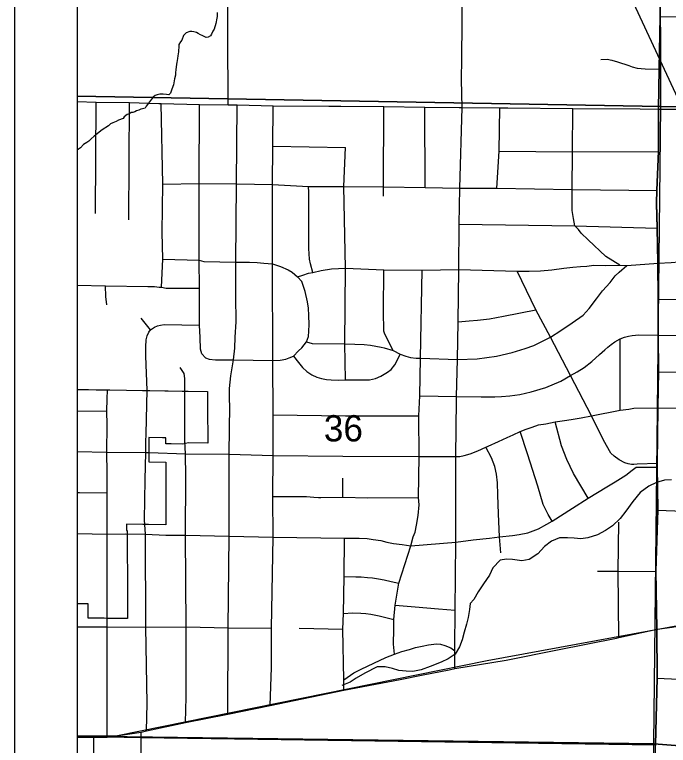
# Model space of a CAD drawing. Extents: x 0 to 34, y 0 to 22.
# Drawn here: x 2 to 3.043, y 17.481 to 18.646 of the extents above; entities that cross this region are included whole.
import ezdxf

# ---------------------------------------------------------------- set-up
doc = ezdxf.new("R2010")
doc.units = 0
for name, color, linetype in [('Default', 7, 'Continuous'), ('GM_X_City_Street', 7, 'Continuous'), ('GM_X_County_Road', 7, 'Continuous'), ('GM_X_Minor_River', 7, 'Continuous'), ('GM_X_Rail_Line', 7, 'Continuous'), ('GM_X_Section', 7, 'Continuous'), ('GM_X_Section_Text', 7, 'Continuous'), ('GM_X_State_Route', 7, 'Continuous'), ('GM_X_Township_Road', 7, 'Continuous'), ('SH_Data', 7, 'Continuous')]:
    doc.layers.add(name, color=color, linetype=linetype)

msp = doc.modelspace()

# ---------------------------------------------------------------- linework, layer by layer
at = {"layer": 'Default'}
for points in [[(2.1, 19.5288), (2.1, 18.5156), (3.031, 18.499), (3.0286, 19.513)], [(2.1, 18.5156), (2.1, 17.4954), (3.0196, 17.4831), (3.031, 18.499)], [(2.1, 17.4954), (2.1, 16.4848), (3.0135, 16.4807), (3.0196, 17.4831)]]:
    msp.add_lwpolyline(points, close=True, dxfattribs=at)
at = {"layer": 'GM_X_City_Street'}
for p, q in [((2.1292, 18.3284), (2.13, 18.5064)), ((2.1821, 18.3185), (2.1832, 18.5054)), ((2.6548, 18.3703), (2.6545, 18.498)), ((2.4119, 18.4361), (2.5277, 18.4338)), ((3.0267, 18.1921), (3.175, 18.191)), ((2.2168, 18.1432), (2.2018, 18.1617)), ((2.9657, 18.0149), (2.9659, 18.1287)), ((3.0274, 18.0763), (3.2293, 18.0741)), ((2.2717, 17.9656), (2.2717, 18.0468)), ((2.7037, 17.9414), (2.705, 18.0308)), ((2.1, 18.0141), (2.1469, 18.0136)), ((2.5236, 17.8765), (2.5233, 17.9067)), ((2.4537, 17.6674), (2.5237, 17.6662))]:
    msp.add_line(p, q, dxfattribs=at)
for points in [[(2.3406, 18.5021), (2.3402, 18.6139), (2.3402, 18.7243), (2.3385, 18.7535)], [(2.7084, 18.2392), (2.7093, 18.3118), (2.7104, 18.369), (2.7138, 18.4976), (2.7129, 18.542), (2.7136, 18.5759), (2.7151, 18.7475)], [(3.03, 18.6425), (3.0728, 18.6421), (3.1315, 18.6402), (3.1893, 18.6388), (3.247, 18.6395), (3.3045, 18.6389), (3.3629, 18.6394), (3.4213, 18.6393), (3.4792, 18.6387), (3.537, 18.639), (3.5995, 18.6384)], [(2.9349, 18.5741), (2.945, 18.5745), (2.9525, 18.5733), (2.9618, 18.5707), (2.9797, 18.5648), (2.9849, 18.5625), (2.9928, 18.5603), (3.0058, 18.5592), (3.0286, 18.5588)], [(2.2345, 18.211), (2.2366, 18.256), (2.2352, 18.2988), (2.2366, 18.3756), (2.234, 18.5038)], [(2.2943, 18.2545), (2.2942, 18.3765), (2.295, 18.5027)], [(2.3401, 17.5303), (2.3405, 17.6682), (2.3421, 17.8145), (2.3425, 17.9449), (2.3429, 17.9858), (2.3434, 18.0206), (2.3429, 18.0338), (2.3429, 18.0495), (2.3448, 18.0696), (2.3492, 18.0953), (2.3511, 18.1142), (2.352, 18.1316), (2.3533, 18.156), (2.3529, 18.1966), (2.3527, 18.2511), (2.3542, 18.3757), (2.355, 18.502)], [(2.4074, 17.5441), (2.4098, 17.6046), (2.4098, 17.6673), (2.4126, 17.8125), (2.4118, 17.8774), (2.4126, 17.943), (2.4126, 18.0079), (2.4118, 18.0942), (2.4113, 18.2482), (2.4113, 18.3749), (2.4119, 18.4361), (2.4123, 18.5004)], [(2.5886, 18.3565), (2.5886, 18.3712), (2.5887, 18.4991)], [(2.7693, 18.3693), (2.7728, 18.4278), (2.774, 18.4971)], [(2.9654, 18.2464), (2.9433, 18.2603), (2.9148, 18.2865), (2.9038, 18.2974), (2.8996, 18.3029), (2.8937, 18.3092), (2.8916, 18.3205), (2.8892, 18.3333), (2.8895, 18.367), (2.8899, 18.4269), (2.8904, 18.4959)], [(2.5279, 18.0633), (2.5269, 18.1208), (2.5279, 18.2417), (2.5254, 18.3716), (2.5277, 18.4338)], [(2.7728, 18.4278), (2.8899, 18.4269), (3.0272, 18.4275)], [(2.2366, 18.3756), (2.2942, 18.3765), (2.3542, 18.3757), (2.4113, 18.3749), (2.469, 18.3717), (2.5254, 18.3716), (2.5886, 18.3712), (2.6548, 18.3703), (2.7104, 18.369), (2.7693, 18.3693), (2.8895, 18.367), (3.0247, 18.3652)], [(2.4758, 18.2346), (2.4721, 18.2485), (2.4705, 18.2559), (2.4692, 18.2729), (2.4692, 18.3626), (2.469, 18.3717)], [(2.7093, 18.3118), (2.8937, 18.3092), (3.025, 18.3054)], [(3.0264, 18.2497), (3.0471, 18.2507), (3.0593, 18.2515), (3.1066, 18.2545), (3.1459, 18.257), (3.1658, 18.2583), (3.186, 18.2587), (3.2256, 18.2585), (3.2449, 18.2586), (3.3031, 18.2593), (3.3486, 18.2586), (3.4109, 18.2586), (3.4741, 18.2578), (3.5366, 18.2577), (3.6004, 18.2571), (3.6644, 18.2564), (3.7333, 18.2568), (3.7941, 18.2554)], [(2.2366, 18.256), (2.2943, 18.2545), (2.3019, 18.2522), (2.3527, 18.2511), (2.3747, 18.2511), (2.3868, 18.2506), (2.3978, 18.2495), (2.4113, 18.2482), (2.4241, 18.244), (2.4362, 18.239), (2.4428, 18.2352), (2.4512, 18.2277), (2.4599, 18.2306)], [(2.2948, 18.1548), (2.2951, 18.2094), (2.2943, 18.2545)], [(2.2985, 18.1048), (2.3043, 18.0986), (2.3104, 18.0964), (2.3202, 18.0953), (2.3492, 18.0953), (2.4118, 18.0942), (2.4236, 18.0948), (2.4329, 18.0964), (2.4378, 18.0986), (2.4449, 18.1013), (2.4531, 18.1095), (2.4581, 18.1145), (2.4657, 18.1238), (2.4745, 18.1216), (2.5269, 18.1208), (2.5429, 18.1205), (2.5576, 18.1199), (2.5675, 18.1188), (2.5845, 18.1155), (2.5894, 18.1145), (2.6036, 18.1101), (2.6151, 18.1046), (2.6239, 18.1013), (2.6315, 18.0991), (2.6403, 18.098), (2.6474, 18.098), (2.7064, 18.0959), (2.7377, 18.0971), (2.7687, 18.1011), (2.7935, 18.1069), (2.8143, 18.1135), (2.828, 18.1184), (2.8546, 18.1317), (2.8714, 18.1419), (2.8896, 18.1543), (2.9069, 18.1667), (2.9166, 18.1773), (2.9281, 18.1928), (2.9379, 18.2052), (2.9498, 18.2185), (2.9582, 18.2291), (2.9644, 18.2353), (2.9768, 18.2459)], [(2.4599, 18.2306), (2.4686, 18.2335), (2.4758, 18.2346), (2.4889, 18.2379), (2.5054, 18.2407), (2.5279, 18.2417), (2.5889, 18.239), (2.6499, 18.2385), (2.7084, 18.2392), (2.8016, 18.2369), (2.821, 18.2369), (2.8391, 18.2373), (2.8569, 18.2389), (2.8763, 18.2414), (2.8903, 18.2431), (2.9027, 18.2443), (2.9126, 18.2447), (2.9237, 18.2464), (2.9418, 18.246), (2.9654, 18.2464), (2.9768, 18.2459), (3.0264, 18.2497)], [(2.6036, 18.1101), (2.5978, 18.1212), (2.5936, 18.1304), (2.5907, 18.1362), (2.589, 18.1412), (2.5882, 18.1729), (2.5889, 18.239)], [(2.6059, 17.6263), (2.6045, 17.6421), (2.605, 17.6662), (2.605, 17.6814), (2.6071, 17.704), (2.6129, 17.7391), (2.632, 17.7989), (2.636, 17.8131), (2.6387, 17.8207), (2.6413, 17.8316), (2.6436, 17.847), (2.6451, 17.864), (2.6443, 17.8761), (2.6452, 17.941), (2.6449, 18.0062), (2.6462, 18.0378), (2.6474, 18.098), (2.6499, 18.2385)], [(2.705, 18.0308), (2.7051, 18.0367), (2.7064, 18.0959), (2.7077, 18.1557), (2.7084, 18.2392)], [(3.0254, 17.9302), (2.9929, 17.929), (2.988, 17.9287), (2.9838, 17.9287), (2.9788, 17.9298), (2.9735, 17.9313), (2.9644, 17.9359), (2.9564, 17.9416), (2.9511, 17.9465), (2.9393, 17.9675), (2.92, 18.0059), (2.8868, 18.0702), (2.8546, 18.1317), (2.8316, 18.1751), (2.8016, 18.2369)], [(2.4657, 18.1238), (2.4687, 18.1325), (2.4695, 18.141), (2.47, 18.1517), (2.4695, 18.1662), (2.4687, 18.1777), (2.4674, 18.188), (2.4635, 18.2042), (2.4584, 18.22), (2.4512, 18.2277)], [(2.1, 18.2145), (2.1452, 18.2132), (2.2123, 18.2125), (2.2229, 18.2121), (2.2304, 18.2111), (2.2345, 18.211), (2.2419, 18.2094), (2.2951, 18.2094)], [(2.1473, 18.183), (2.1456, 18.1961), (2.1452, 18.2132)], [(2.7077, 18.1557), (2.7253, 18.1578), (2.7384, 18.1588), (2.7577, 18.1609), (2.7798, 18.165), (2.8316, 18.1751)], [(2.2985, 18.1048), (2.2964, 18.1125), (2.296, 18.131), (2.2948, 18.1509), (2.2948, 18.1548)], [(2.2114, 18.0472), (2.2095, 18.1013), (2.2095, 18.1163), (2.2098, 18.1275), (2.2112, 18.1338), (2.214, 18.1397), (2.2168, 18.1432)], [(2.2168, 18.1432), (2.2231, 18.1474), (2.228, 18.1495), (2.2329, 18.1505), (2.2384, 18.1516), (2.2948, 18.1509)], [(2.6462, 18.0378), (2.7051, 18.0367), (2.744, 18.0364), (2.766, 18.0364), (2.7767, 18.0368), (2.7902, 18.0382), (2.8058, 18.04), (2.8239, 18.0443), (2.8474, 18.051), (2.8712, 18.0613), (2.8868, 18.0702), (2.8976, 18.0761), (2.9083, 18.0832), (2.9206, 18.0929), (2.9332, 18.1039), (2.9413, 18.1112), (2.946, 18.1154), (2.9518, 18.1196), (2.9575, 18.1238), (2.9659, 18.1287), (2.9727, 18.1314), (2.9793, 18.1332), (2.985, 18.1342), (2.9955, 18.135), (3.027, 18.1345), (3.2027, 18.1316)], [(2.4449, 18.1013), (2.4528, 18.0911), (2.4594, 18.083), (2.4659, 18.0768), (2.4741, 18.0715), (2.4823, 18.0678), (2.4896, 18.0654), (2.4974, 18.0642), (2.5051, 18.0633), (2.517, 18.0629), (2.5279, 18.0633), (2.537, 18.0637), (2.5485, 18.0633), (2.5579, 18.0633), (2.566, 18.0633), (2.5758, 18.0658), (2.5844, 18.0691), (2.5947, 18.0756), (2.6004, 18.0801), (2.6065, 18.0875), (2.6118, 18.0973), (2.6151, 18.1046)], [(2.2717, 18.0468), (2.2717, 18.0656), (2.2706, 18.0735), (2.2642, 18.0829)], [(2.1479, 17.6814), (2.1476, 17.7279), (2.1476, 17.7583), (2.1475, 17.7977), (2.1477, 17.8175), (2.1474, 17.8833), (2.1475, 17.9147), (2.1473, 17.9481), (2.1475, 17.9915), (2.1469, 18.0136), (2.1477, 18.0331), (2.1484, 18.0469)], [(2.2094, 17.9647), (2.2096, 17.9772), (2.2114, 18.0472)], [(2.2148, 17.9474), (2.2725, 17.9456), (2.3425, 17.9449), (2.4126, 17.943), (2.5234, 17.9417), (2.6452, 17.941), (2.7037, 17.9414), (2.7103, 17.9415), (2.7172, 17.943), (2.7268, 17.9457), (2.7391, 17.9505), (2.7516, 17.9561), (2.7554, 17.9578), (2.772, 17.9653), (2.7858, 17.9716), (2.7954, 17.9758), (2.8066, 17.9809), (2.8159, 17.9849), (2.8255, 17.9882), (2.8359, 17.9915), (2.8472, 17.9933), (2.8622, 17.9964), (2.8809, 17.999), (2.8908, 18.0008), (2.9038, 18.0029), (2.92, 18.0059), (2.9657, 18.0149), (2.98, 18.0168), (2.9879, 18.0183), (3.0262, 18.019), (3.2285, 18.0154)], [(2.4126, 18.0079), (2.5278, 18.0062), (2.6449, 18.0062)], [(2.9149, 17.875), (2.8914, 17.914), (2.8806, 17.9365), (2.8724, 17.9581), (2.8622, 17.9964)], [(2.8575, 17.8384), (2.851, 17.8487), (2.8433, 17.8646), (2.8345, 17.8942), (2.8179, 17.9456), (2.8066, 17.9809)], [(2.2724, 17.5173), (2.2734, 17.5577), (2.2734, 17.6264), (2.2734, 17.6697), (2.2724, 17.8156), (2.2733, 17.9088), (2.2725, 17.9456), (2.2717, 17.9656)], [(2.2071, 17.8403), (2.2084, 17.9039), (2.2091, 17.9476), (2.2094, 17.9647)], [(2.7754, 17.7878), (2.7732, 17.8132), (2.7718, 17.8499), (2.7706, 17.88), (2.7701, 17.8995), (2.7689, 17.9131), (2.7659, 17.9255), (2.7606, 17.9391), (2.7516, 17.9561)], [(2.1, 17.9491), (2.1473, 17.9481), (2.2091, 17.9476), (2.2148, 17.9474)], [(2.7021, 17.6032), (2.702, 17.6313), (2.702, 17.6365), (2.7028, 17.6964), (2.7037, 17.8047), (2.7037, 17.9414)], [(2.1774, 17.8178), (2.2086, 17.8174), (2.2411, 17.816), (2.2724, 17.8156), (2.3421, 17.8145), (2.4126, 17.8125), (2.5263, 17.8108), (2.5347, 17.8109), (2.5425, 17.8109), (2.5495, 17.8109), (2.5624, 17.8105), (2.5721, 17.8091), (2.5841, 17.8073), (2.5937, 17.8045), (2.6044, 17.8026), (2.6182, 17.8008), (2.632, 17.7989), (2.7037, 17.8047), (2.7313, 17.8084), (2.7574, 17.811), (2.7732, 17.8132), (2.7944, 17.8154), (2.805, 17.8168), (2.8187, 17.8198), (2.8355, 17.826), (2.8487, 17.8335), (2.8575, 17.8384), (2.8897, 17.8591), (2.9149, 17.875), (2.9449, 17.8931), (2.9577, 17.9006), (2.9749, 17.9116), (2.985, 17.9196), (2.9912, 17.924), (3.0253, 17.9245)], [(2.1, 17.884), (2.1037, 17.8839), (2.1474, 17.8833)], [(2.4118, 17.8774), (2.4514, 17.8774), (2.4655, 17.8774), (2.4771, 17.8763), (2.485, 17.876), (2.4883, 17.876), (2.5236, 17.8765), (2.5633, 17.8756), (2.6443, 17.8761)], [(3.0262, 17.8555), (3.0936, 17.8529), (3.161, 17.8524), (3.2284, 17.8538), (3.2962, 17.8533), (3.3626, 17.8529), (3.431, 17.8519), (3.4979, 17.8509), (3.5318, 17.8514)], [(2.2102, 17.5038), (2.2112, 17.5476), (2.2093, 17.6692), (2.2086, 17.8174), (2.2071, 17.8403)], [(2.9637, 17.6526), (2.9626, 17.7586), (2.9637, 17.8366)], [(2.1, 17.8184), (2.1477, 17.8175), (2.1774, 17.8178)], [(2.5253, 17.5688), (2.525, 17.5854), (2.5237, 17.6662), (2.5244, 17.6912), (2.5257, 17.7497), (2.5263, 17.8108)], [(2.9298, 17.7584), (2.9626, 17.7586), (3.0231, 17.7581)], [(2.5257, 17.7497), (2.5443, 17.7495), (2.5529, 17.7492), (2.5631, 17.7484), (2.5709, 17.7476), (2.5804, 17.7464), (2.5896, 17.7445), (2.6008, 17.7422), (2.6129, 17.7391)], [(2.6071, 17.704), (2.639, 17.7016), (2.676, 17.6986), (2.7028, 17.6964)], [(2.5244, 17.6912), (2.5388, 17.6919), (2.5525, 17.6914), (2.5601, 17.6907), (2.5681, 17.6897), (2.5817, 17.6872), (2.5964, 17.6837), (2.605, 17.6814)], [(2.1478, 17.4937), (2.1479, 17.6696), (2.1479, 17.6814)], [(2.1, 17.6697), (2.1479, 17.6696), (2.2093, 17.6692), (2.2734, 17.6697), (2.3405, 17.6682), (2.4098, 17.6673)], [(2.6931, 17.6014), (2.7021, 17.6032), (2.784, 17.6167), (2.866, 17.6329), (2.9599, 17.6518), (2.9637, 17.6526), (3.0249, 17.6659), (3.0489, 17.669), (3.0547, 17.6702)], [(2.525, 17.5854), (2.541, 17.5962), (2.5528, 17.6024), (2.573, 17.6117), (2.5922, 17.6207), (2.6059, 17.6263), (2.6177, 17.6301), (2.6301, 17.6338), (2.6397, 17.6366), (2.65, 17.6387), (2.6602, 17.6412), (2.6686, 17.6422), (2.6726, 17.6428), (2.6792, 17.6419), (2.686, 17.64), (2.6956, 17.6363), (2.702, 17.6313)], [(2.2017, 17.5019), (2.2102, 17.5038), (2.2724, 17.5173), (2.3401, 17.5303), (2.4074, 17.5441), (2.5253, 17.5688), (2.6148, 17.5857), (2.6518, 17.5931), (2.6931, 17.6014)], [(3.0251, 17.5877), (3.0931, 17.5844), (3.1601, 17.5816), (3.2165, 17.5798), (3.2276, 17.5802), (3.2576, 17.5779), (3.2955, 17.5793), (3.3626, 17.5947)], [(2.1, 17.4935), (2.1264, 17.4939), (2.1478, 17.4937), (2.2017, 17.5019)], [(2.126, 17.2305), (2.1263, 17.3766), (2.1264, 17.4939)]]:
    msp.add_lwpolyline(points, dxfattribs=at)
at = {"layer": 'GM_X_County_Road'}
for p, q in [((2.9976, 18.4958), (3.0275, 18.495)), ((3.0275, 18.495), (3.086, 18.4948))]:
    msp.add_line(p, q, dxfattribs=at)
for points in [[(3.0224, 17.4801), (3.0224, 17.4808), (3.0251, 17.5877), (3.0249, 17.6659), (3.0231, 17.7581), (3.0262, 17.8555), (3.0253, 17.9245), (3.0254, 17.9302), (3.0262, 18.019), (3.0274, 18.0763), (3.027, 18.1345), (3.0267, 18.1921), (3.0264, 18.2497), (3.025, 18.3054), (3.0239, 18.3446), (3.0247, 18.3652), (3.0272, 18.4275), (3.0275, 18.495), (3.0286, 18.5588), (3.03, 18.6425), (3.0302, 18.7798)], [(2.1, 18.507), (2.13, 18.5064), (2.1832, 18.5054), (2.23, 18.5039)], [(2.23, 18.5039), (2.234, 18.5038), (2.295, 18.5027), (2.3406, 18.5021), (2.355, 18.502), (2.4123, 18.5004), (2.5013, 18.4999), (2.5202, 18.4998)], [(2.5202, 18.4998), (2.5887, 18.4991), (2.6545, 18.498), (2.7089, 18.4977)], [(2.7089, 18.4977), (2.7138, 18.4976), (2.774, 18.4971), (2.7869, 18.497), (2.8904, 18.4959), (2.9976, 18.4958)], [(2.2008, 17.3809), (2.2014, 17.4312), (2.2017, 17.4929), (2.2017, 17.5019)]]:
    msp.add_lwpolyline(points, dxfattribs=at)
at = {"layer": 'GM_X_Minor_River'}
for points in [[(2.3231, 18.649), (2.323, 18.6426), (2.3226, 18.6399), (2.3209, 18.6316), (2.3181, 18.6225), (2.3161, 18.6195), (2.3138, 18.6146), (2.3126, 18.612), (2.3087, 18.6098), (2.3057, 18.6091), (2.3023, 18.6106), (2.2993, 18.6122), (2.2963, 18.6134)], [(2.2963, 18.6134), (2.2929, 18.6158), (2.2903, 18.6173), (2.2861, 18.6182), (2.2827, 18.619), (2.2793, 18.6187), (2.2739, 18.6165), (2.2693, 18.6124), (2.2665, 18.6052), (2.2646, 18.6026), (2.2622, 18.5981), (2.2617, 18.5931), (2.2613, 18.5889), (2.2612, 18.5863), (2.2604, 18.5798), (2.2599, 18.5757), (2.2586, 18.5692), (2.2582, 18.5666), (2.2573, 18.5575), (2.2568, 18.5537), (2.2564, 18.5491), (2.2551, 18.5431), (2.2542, 18.537), (2.2534, 18.5336), (2.251, 18.5268), (2.2498, 18.5238), (2.2486, 18.5204), (2.2459, 18.5181), (2.2425, 18.5182), (2.2372, 18.5187), (2.2346, 18.5191), (2.2315, 18.5188), (2.2273, 18.5177), (2.2243, 18.5166), (2.2208, 18.5144), (2.2181, 18.5107), (2.215, 18.5069), (2.2119, 18.5024), (2.2099, 18.4998), (2.208, 18.4968), (2.2038, 18.4957), (2.2011, 18.495), (2.1984, 18.4935), (2.1946, 18.4924), (2.1919, 18.491), (2.1888, 18.4899), (2.1858, 18.4896), (2.1831, 18.4873), (2.1797, 18.4866), (2.1747, 18.4829), (2.1731, 18.4803), (2.1655, 18.4774), (2.162, 18.4752), (2.1567, 18.4734), (2.1532, 18.4715), (2.1497, 18.4685), (2.1397, 18.4622), (2.1351, 18.4582), (2.1317, 18.4559), (2.127, 18.4522), (2.122, 18.4477), (2.1182, 18.444), (2.1151, 18.4418), (2.1097, 18.4385), (2.1051, 18.4336), (2.102, 18.431), (2.1, 18.4298)], [(3.0477, 17.904), (3.0367, 17.9034), (3.0241, 17.8999), (3.0114, 17.8937), (2.9976, 17.884), (2.9859, 17.8694), (2.9749, 17.8541), (2.966, 17.8424), (2.9536, 17.8309), (2.9428, 17.8231), (2.9297, 17.8165), (2.9141, 17.8115), (2.903, 17.8102), (2.8924, 17.8112), (2.8818, 17.8117), (2.8693, 17.8116), (2.8566, 17.8065), (2.8454, 17.7976), (2.8346, 17.786), (2.8207, 17.7768), (2.8089, 17.7751), (2.7941, 17.7769), (2.7846, 17.7775), (2.7743, 17.7762), (2.7627, 17.7638), (2.7575, 17.7522), (2.7481, 17.7383), (2.7395, 17.7255), (2.7324, 17.7135)], [(2.7324, 17.7135), (2.7266, 17.7068), (2.7256, 17.6973), (2.7235, 17.6848), (2.7206, 17.6739), (2.7173, 17.661), (2.714, 17.6489), (2.7096, 17.638), (2.7025, 17.6263), (2.6917, 17.6189), (2.6802, 17.6131), (2.6629, 17.6062), (2.6487, 17.6012), (2.6353, 17.5984), (2.6247, 17.599), (2.6129, 17.6003), (2.6027, 17.6032), (2.5909, 17.6057), (2.5784, 17.606), (2.5584, 17.5957), (2.5449, 17.5876), (2.5352, 17.5817), (2.5218, 17.5763)]]:
    msp.add_lwpolyline(points, dxfattribs=at)
at = {"layer": 'GM_X_Rail_Line'}
for points in [[(2.3898, 19.7064), (2.7075, 19.2523), (2.7388, 19.2043), (2.765, 19.1563), (2.8452, 18.9696), (3.1958, 18.2158), (3.251, 18.1014), (3.28, 18.041), (3.3284, 17.9975), (3.3695, 17.9588), (3.4444, 17.9225), (3.727, 17.8039), (4.0235, 17.6837)], [(2.1, 17.4966), (2.1615, 17.4961), (2.7539, 17.6159), (3.1854, 17.6954), (3.727, 17.8039)]]:
    msp.add_lwpolyline(points, dxfattribs=at)
at = {"layer": 'GM_X_Section'}
for points in [[(3.0286, 19.513), (4.0509, 19.5018), (4.0528, 18.4887), (3.031, 18.499)], [(3.031, 18.499), (4.0528, 18.4887), (4.0485, 17.4495), (3.1709, 17.4714), (3.0196, 17.4831)], [(3.0196, 17.4831), (3.1709, 17.4714), (4.0485, 17.4495), (4.0113, 16.4768), (3.0135, 16.4807)]]:
    msp.add_lwpolyline(points, close=True, dxfattribs=at)
at = {"layer": 'GM_X_State_Route'}
msp.add_lwpolyline([(2.1, 18.7586), (2.1, 18.0483), (2.1057, 18.0482), (2.1078, 18.0482), (2.118, 18.048), (2.1303, 18.0478), (2.1425, 18.0475), (2.1472, 18.0475), (2.152, 18.0474), (2.1786, 18.0469), (2.204, 18.0465), (2.2051, 18.0464), (2.208, 18.0464), (2.2097, 18.0464), (2.2146, 18.0463), (2.2157, 18.0463), (2.2394, 18.0458), (2.2411, 18.0458), (2.2447, 18.0458), (2.2675, 18.0454), (2.2724, 18.0453), (2.277, 18.0452), (2.3079, 18.0447), (2.3079, 18.033), (2.3079, 18.0213), (2.3079, 18.0095), (2.3079, 18.0073), (2.3079, 17.9978), (2.308, 17.9861), (2.308, 17.9767), (2.308, 17.9744), (2.308, 17.9685), (2.308, 17.9665), (2.308, 17.9627), (2.2773, 17.9633), (2.2726, 17.9622), (2.2678, 17.9611), (2.2497, 17.9614), (2.2411, 17.9615), (2.2411, 17.971), (2.236, 17.9711), (2.2143, 17.9714), (2.2143, 17.962), (2.2143, 17.9527), (2.2143, 17.9493), (2.2143, 17.9481), (2.2142, 17.9432), (2.2142, 17.9328), (2.2411, 17.9323), (2.2411, 17.9198), (2.2411, 17.9074), (2.2411, 17.8949), (2.2411, 17.8699), (2.2411, 17.8574), (2.2411, 17.8498), (2.2411, 17.8449), (2.2411, 17.8386), (2.2411, 17.8324), (2.2138, 17.8329), (2.2094, 17.833), (2.2044, 17.8331), (2.1783, 17.8336), (2.1783, 17.8247), (2.1783, 17.8232), (2.1797, 17.8232), (2.1797, 17.8137), (2.1798, 17.8042), (2.1798, 17.7967), (2.1798, 17.7891), (2.1798, 17.7815), (2.1799, 17.7588), (2.1799, 17.7513), (2.1799, 17.7437), (2.18, 17.7361), (2.18, 17.7285), (2.1801, 17.7058), (2.1801, 17.6907), (2.1801, 17.6831), (2.1786, 17.6831), (2.1771, 17.6831), (2.1522, 17.6829), (2.1473, 17.6832), (2.1427, 17.6835), (2.1174, 17.6837), (2.1174, 17.6911), (2.1174, 17.6987), (2.1174, 17.7062), (2.1067, 17.7063), (2.1, 17.7063), (2.1, 17.2361)], dxfattribs=at)
at = {"layer": 'GM_X_Township_Road'}
for points in [[(2.1, 20.9), (2.1, 17.494), (2.1261, 17.4945), (2.1476, 17.4943), (2.2015, 17.4935), (3.0222, 17.4813), (3.0249, 17.5882), (3.0246, 17.6664), (3.0229, 17.7586), (3.026, 17.856), (3.0251, 17.9251), (3.0251, 17.9307), (3.026, 18.0195), (3.0271, 18.0768), (3.0268, 18.1351), (3.0265, 18.1926), (3.0262, 18.2502), (3.0247, 18.3059), (3.0237, 18.3452), (3.0245, 18.3657), (3.027, 18.428), (3.0273, 18.4955), (3.0284, 18.5593), (3.0298, 18.643), (3.03, 18.7804)], [(3.03, 18.7804), (3.0298, 18.643), (3.0284, 18.5593), (3.0273, 18.4955), (3.027, 18.428), (3.0245, 18.3657), (3.0237, 18.3452), (3.0247, 18.3059), (3.0262, 18.2502), (3.0265, 18.1926), (3.0268, 18.1351), (3.0271, 18.0768), (3.026, 18.0195), (3.0251, 17.9307), (3.0251, 17.9251), (3.026, 17.856), (3.0229, 17.7586), (3.0246, 17.6664), (3.0249, 17.5882), (3.0222, 17.4813), (3.0222, 17.4806)], [(3.0233, 15.5768), (3.0198, 16.3586), (3.018, 16.4163), (3.0163, 16.6061), (3.0141, 16.8752), (3.0141, 16.8793), (3.0149, 17.0299), (3.0151, 17.0528), (3.0151, 17.0635), (3.0153, 17.0702), (3.0204, 17.2302), (3.021, 17.2383), (3.0221, 17.3705), (3.0222, 17.3748), (3.0222, 17.4806), (3.0222, 17.4813), (2.2015, 17.4935), (2.1476, 17.4943), (2.1261, 17.4945), (2.1, 17.494), (2.1, 14.1)]]:
    msp.add_lwpolyline(points, dxfattribs=at)
at = {"layer": 'SH_Data'}
for p, q in [((2, 21), (2, 14)), ((2.1, 20.9), (2.1, 14.1))]:
    msp.add_line(p, q, dxfattribs=at)

# ---------------------------------------------------------------- texts
at = {"layer": 'GM_X_Section_Text'}
msp.add_text('36', height=0.04186, rotation=0, dxfattribs=at).set_placement((2.4933, 17.9653))

doc.saveas('drawing.dxf')
